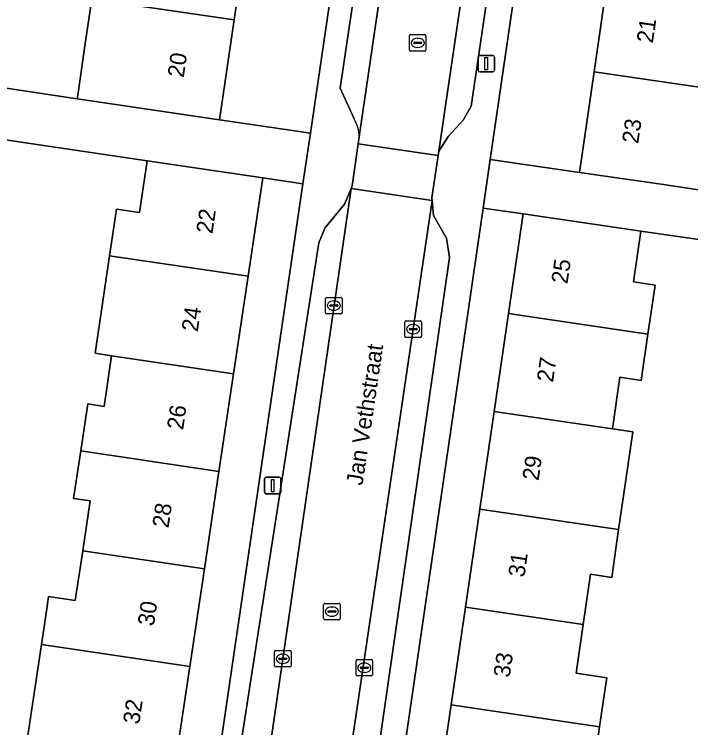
# Model space of a CAD drawing. Extents: x 163683 to 164494, y 382709 to 383872.
# Drawn here: x 164127.96 to 164168.99, y 382929.41 to 382972.71 of the extents above; entities that cross this region are included whole.
import ezdxf

# ---------------------------------------------------------------- set-up
doc = ezdxf.new("R2010")
doc.units = 0
for name, color, linetype in [('IMGEO_Erf', 7, 'Continuous'), ('IMGEO_Kolk', 7, 'Continuous'), ('IMGEO_Lichtmast', 7, 'Continuous'), ('IMGEO_Openbare_ruimte_label', 7, 'Continuous'), ('IMGEO_Pand', 7, 'Continuous'), ('IMGEO_Pand_nummerreeks', 7, 'Continuous'), ('IMGEO_Parkeervlak_open', 7, 'Continuous'), ('IMGEO_Rijbaan_lokaal_open', 7, 'Continuous'), ('IMGEO_Rioolput', 7, 'Continuous'), ('IMGEO_Voetpad_open', 7, 'Continuous')]:
    doc.layers.add(name, color=color, linetype=linetype)

msp = doc.modelspace()

# ---------------------------------------------------------------- linework, layer by layer
at = {"layer": 'IMGEO_Erf'}
for points in [[(164150.98, 383000), (164151.195, 383001.469), (164145.689, 383002.289), (164145.353, 383000), (164144.775, 382996.057), (164143.907, 382990.134), (164143.039, 382984.212), (164142.171, 382978.289), (164141.303, 382972.366), (164140.413, 382966.297), (164145.92, 382965.49)], [(164165.72, 382987.017), (164166.584, 382992.955), (164167.47, 382999.044), (164162.059, 382999.803), (164156.836, 382963.9), (164162.243, 382963.113), (164163.129, 382969.204), (164163.993, 382975.142), (164164.857, 382981.08)], [(164145.469, 382962.412), (164143.034, 382962.775), (164142.144, 382956.805), (164141.26, 382950.884), (164140.377, 382944.964), (164139.494, 382939.044), (164138.611, 382933.124), (164137.706, 382927.054), (164140.229, 382926.679)], [(164157.067, 382948.608), (164157.939, 382954.544), (164158.826, 382960.588), (164156.406, 382960.944), (164151.193, 382925.112), (164153.565, 382924.757), (164154.452, 382930.798), (164155.324, 382936.735), (164156.195, 382942.671)]]:
    msp.add_lwpolyline(points, close=True, dxfattribs=at)
for points in [[(164124.755, 382977.888), (164123.807, 382971.646), (164127.214, 382971.131), (164126.79, 382968.33), (164131.776, 382967.569), (164131.811, 382967.807), (164132.27, 382970.928), (164132.669, 382973.639)], [(164128.706, 382928.397), (164129.611, 382934.465), (164129.912, 382936.48), (164130.044, 382937.367), (164131.662, 382937.125), (164132.112, 382940.144), (164132.564, 382943.175), (164131.561, 382943.325), (164131.992, 382946.215), (164132.417, 382949.06), (164133.404, 382948.913), (164133.862, 382951.987), (164132.861, 382952.136), (164133.331, 382955.286), (164133.744, 382958.057), (164134.167, 382960.889), (164135.555, 382960.682), (164136.023, 382963.821), (164126.324, 382965.242)], [(164174.952, 382958.25), (164165.962, 382959.54), (164165.515, 382956.464), (164166.828, 382956.273), (164166.395, 382953.298), (164165.987, 382950.489), (164164.702, 382950.676), (164164.247, 382947.549), (164165.482, 382947.367), (164165.059, 382944.456), (164164.619, 382941.43), (164164.198, 382938.536), (164162.91, 382938.724), (164162.468, 382935.682), (164162.037, 382932.72), (164163.906, 382932.447), (164163.768, 382931.519), (164163.462, 382929.47), (164163.03, 382926.573)]]:
    msp.add_lwpolyline(points, dxfattribs=at)
at = {"layer": 'IMGEO_Kolk'}
for p, q in [((164146.841, 382954.601), (164146.841, 382955.453)), ((164146.916, 382955.527), (164147.768, 382955.527)), ((164147.842, 382955.453), (164147.842, 382954.601)), ((164147.1, 382955.021), (164147.1, 382955.033)), ((164147.538, 382954.984), (164147.14, 382954.984)), ((164147.143, 382955.07), (164147.541, 382955.07)), ((164147.329, 382955.307), (164147.354, 382955.307)), ((164147.584, 382955.033), (164147.584, 382955.021)), ((164147.768, 382954.527), (164146.916, 382954.527)), ((164147.352, 382954.747), (164147.327, 382954.747)), ((164151.732, 382954.099), (164152.584, 382954.099)), ((164151.657, 382953.173), (164151.657, 382954.025)), ((164152.145, 382953.879), (164152.17, 382953.879)), ((164152.658, 382954.025), (164152.658, 382953.173)), ((164151.916, 382953.593), (164151.916, 382953.605)), ((164152.354, 382953.556), (164151.956, 382953.556)), ((164151.959, 382953.642), (164152.357, 382953.642)), ((164152.168, 382953.319), (164152.143, 382953.319)), ((164152.4, 382953.605), (164152.4, 382953.593)), ((164152.584, 382953.099), (164151.732, 382953.099)), ((164143.747, 382933.171), (164143.747, 382934.023)), ((164143.822, 382934.097), (164144.674, 382934.097)), ((164144.235, 382933.877), (164144.26, 382933.877)), ((164144.748, 382934.023), (164144.748, 382933.171)), ((164144.006, 382933.591), (164144.006, 382933.603)), ((164144.444, 382933.554), (164144.046, 382933.554)), ((164144.049, 382933.64), (164144.447, 382933.64)), ((164144.258, 382933.317), (164144.233, 382933.317)), ((164144.49, 382933.603), (164144.49, 382933.591)), ((164148.696, 382932.624), (164148.696, 382933.476)), ((164148.771, 382933.55), (164149.623, 382933.55)), ((164149.184, 382933.33), (164149.209, 382933.33)), ((164149.697, 382933.476), (164149.697, 382932.624)), ((164144.674, 382933.097), (164143.822, 382933.097)), ((164148.955, 382933.044), (164148.955, 382933.056)), ((164149.393, 382933.007), (164148.995, 382933.007)), ((164148.998, 382933.093), (164149.396, 382933.093)), ((164149.439, 382933.056), (164149.439, 382933.044)), ((164149.623, 382932.55), (164148.771, 382932.55)), ((164149.207, 382932.77), (164149.182, 382932.77))]:
    msp.add_line(p, q, dxfattribs=at)
for points in [[(164146.841, 382954.601), (164146.841, 382955.453)], [(164146.916, 382955.527), (164147.768, 382955.527)], [(164147.842, 382955.453), (164147.842, 382954.601)], [(164147.768, 382954.527), (164146.916, 382954.527)], [(164151.732, 382954.099), (164152.584, 382954.099)], [(164151.657, 382953.173), (164151.657, 382954.025)], [(164152.658, 382954.025), (164152.658, 382953.173)], [(164152.584, 382953.099), (164151.732, 382953.099)], [(164143.747, 382933.171), (164143.747, 382934.023)], [(164143.822, 382934.097), (164144.674, 382934.097)], [(164144.748, 382934.023), (164144.748, 382933.171)], [(164148.696, 382932.624), (164148.696, 382933.476)], [(164148.771, 382933.55), (164149.623, 382933.55)], [(164149.697, 382933.476), (164149.697, 382932.624)], [(164144.674, 382933.097), (164143.822, 382933.097)], [(164149.623, 382932.55), (164148.771, 382932.55)]]:
    msp.add_lwpolyline(points, dxfattribs=at)
for centre, radius, start, end in [((164146.918, 382955.451), 0.0765, 91.552, 178.448), ((164146.918, 382955.451), 0.0765, 91.552, 178.448), ((164147.766, 382955.451), 0.0765, 1.552, 88.448), ((164147.766, 382955.451), 0.0765, 1.552, 88.448), ((164147.14, 382955.03), 0.0403, 85.8775, 175.7526), ((164147.137, 382955.02), 0.0366, 178.938, 274.7102), ((164147.541, 382955.027), 0.043, 264.8664, 352.4533), ((164147.545, 382955.032), 0.0386, 1.7309, 96.639), ((164146.918, 382954.603), 0.0765, 181.552, 268.448), ((164146.918, 382954.603), 0.0765, 181.552, 268.448), ((164147.766, 382954.603), 0.0765, 271.552, 358.448), ((164147.766, 382954.603), 0.0765, 271.552, 358.448), ((164151.734, 382954.023), 0.0765, 91.552, 178.448), ((164151.734, 382954.023), 0.0765, 91.552, 178.448), ((164152.582, 382954.023), 0.0765, 1.552, 88.448), ((164152.582, 382954.023), 0.0765, 1.552, 88.448), ((164151.956, 382953.602), 0.0403, 85.8775, 175.7526), ((164151.953, 382953.592), 0.0366, 178.938, 274.7102), ((164152.357, 382953.599), 0.043, 264.8664, 352.4533), ((164152.361, 382953.604), 0.0386, 1.7309, 96.639), ((164151.734, 382953.175), 0.0765, 181.552, 268.448), ((164151.734, 382953.175), 0.0765, 181.552, 268.448), ((164152.582, 382953.175), 0.0765, 271.552, 358.448), ((164152.582, 382953.175), 0.0765, 271.552, 358.448), ((164143.824, 382934.021), 0.0765, 91.552, 178.448), ((164143.824, 382934.021), 0.0765, 91.552, 178.448), ((164144.672, 382934.021), 0.0765, 1.552, 88.448), ((164144.672, 382934.021), 0.0765, 1.552, 88.448), ((164144.046, 382933.6), 0.0403, 85.8775, 175.7526), ((164144.043, 382933.59), 0.0366, 178.938, 274.7102), ((164144.447, 382933.597), 0.043, 264.8664, 352.4533), ((164144.451, 382933.602), 0.0386, 1.7309, 96.639), ((164148.773, 382933.474), 0.0765, 91.552, 178.448), ((164148.773, 382933.474), 0.0765, 91.552, 178.448), ((164149.621, 382933.474), 0.0765, 1.552, 88.448), ((164149.621, 382933.474), 0.0765, 1.552, 88.448), ((164143.824, 382933.173), 0.0765, 181.552, 268.448), ((164143.824, 382933.173), 0.0765, 181.552, 268.448), ((164144.672, 382933.173), 0.0765, 271.552, 358.448), ((164144.672, 382933.173), 0.0765, 271.552, 358.448), ((164148.995, 382933.053), 0.0403, 85.8775, 175.7526), ((164148.992, 382933.043), 0.0366, 178.938, 274.7102), ((164149.396, 382933.05), 0.043, 264.8664, 352.4533), ((164149.4, 382933.055), 0.0386, 1.7309, 96.639), ((164148.773, 382932.626), 0.0765, 181.552, 268.448), ((164148.773, 382932.626), 0.0765, 181.552, 268.448), ((164149.621, 382932.626), 0.0765, 271.552, 358.448), ((164149.621, 382932.626), 0.0765, 271.552, 358.448)]:
    msp.add_arc(centre, radius, start, end, dxfattribs=at)
for centre, major_axis, ratio, start_param, end_param in [((164147.328, 382955.027), (-0.387, 0.002), 0.722429, 4.712389, 7.853982), ((164147.353, 382955.027), (-0.39, 0.002), 0.717154, 1.570796, 4.712389), ((164152.144, 382953.599), (-0.387, 0.002), 0.722429, 4.712389, 7.853982), ((164152.169, 382953.599), (-0.39, 0.002), 0.717154, 1.570796, 4.712389), ((164144.234, 382933.597), (-0.387, 0.002), 0.722429, 4.712389, 7.853982), ((164144.259, 382933.597), (-0.39, 0.002), 0.717154, 1.570796, 4.712389), ((164149.183, 382933.05), (-0.387, 0.002), 0.722429, 4.712389, 7.853982), ((164149.208, 382933.05), (-0.39, 0.002), 0.717154, 1.570796, 4.712389)]:
    msp.add_ellipse(centre, major_axis=major_axis, ratio=ratio, start_param=start_param, end_param=end_param, dxfattribs=at)
at = {"layer": 'IMGEO_Lichtmast'}
for p, q in [((164156.193, 382970.205), (164156.983, 382970.205)), ((164156.983, 382970.205), (164156.193, 382970.205)), ((164156.093, 382969.305), (164156.093, 382970.105)), ((164156.093, 382970.105), (164156.093, 382969.305)), ((164157.083, 382970.105), (164157.083, 382969.305)), ((164157.083, 382969.305), (164157.083, 382970.105)), ((164156.983, 382969.205), (164156.193, 382969.205)), ((164156.193, 382969.205), (164156.983, 382969.205)), ((164143.241, 382944.608), (164144.031, 382944.608)), ((164144.031, 382944.608), (164143.241, 382944.608)), ((164143.141, 382943.708), (164143.141, 382944.508)), ((164143.141, 382944.508), (164143.141, 382943.708)), ((164144.131, 382944.508), (164144.131, 382943.708)), ((164144.131, 382943.708), (164144.131, 382944.508)), ((164144.031, 382943.608), (164143.241, 382943.608)), ((164143.241, 382943.608), (164144.031, 382943.608))]:
    msp.add_line(p, q, dxfattribs=at)
for points in [[(164156.513, 382970.08), (164156.663, 382970.08), (164156.663, 382969.33), (164156.513, 382969.33), (164156.513, 382970.08)], [(164143.561, 382944.483), (164143.711, 382944.483), (164143.711, 382943.733), (164143.561, 382943.733), (164143.561, 382944.483)]]:
    msp.add_lwpolyline(points, dxfattribs=at)
for centre, start, end in [((164156.193, 382970.105), 90, 180), ((164156.193, 382970.105), 90, 180), ((164156.983, 382970.105), 0, 90), ((164156.983, 382970.105), 360, 90), ((164156.193, 382969.305), 180, 270), ((164156.193, 382969.305), 180, 270), ((164156.983, 382969.305), 270, 0), ((164156.983, 382969.305), 270, 0), ((164143.241, 382944.508), 90, 180), ((164143.241, 382944.508), 90, 180), ((164144.031, 382944.508), 0, 90), ((164144.031, 382944.508), 360, 90), ((164143.241, 382943.708), 180, 270), ((164143.241, 382943.708), 180, 270), ((164144.031, 382943.708), 270, 0), ((164144.031, 382943.708), 270, 0)]:
    msp.add_arc(centre, 0.1, start, end, dxfattribs=at)
at = {"layer": 'IMGEO_Pand'}
for points in [[(164142.171, 382978.289), (164134.655, 382979.397), (164133.541, 382979.561), (164133.11, 382976.634), (164132.669, 382973.639), (164141.303, 382972.366)], [(164171.25, 382974.086), (164163.993, 382975.142), (164163.129, 382969.204), (164171.591, 382967.973), (164174.826, 382967.502), (164175.221, 382970.212), (164171.985, 382970.683), (164172.016, 382970.894), (164170.811, 382971.069)], [(164141.303, 382972.366), (164132.669, 382973.639), (164132.27, 382970.928), (164131.811, 382967.807), (164131.776, 382967.569), (164132.895, 382967.404), (164135.467, 382967.025), (164140.413, 382966.297)], [(164171.591, 382967.973), (164163.129, 382969.204), (164162.243, 382963.113), (164167.191, 382962.393), (164169.473, 382962.061), (164169.929, 382965.201), (164171.161, 382965.022)], [(164133.744, 382958.057), (164142.144, 382956.805), (164143.034, 382962.775), (164138.089, 382963.513), (164136.023, 382963.821), (164135.555, 382960.682), (164134.167, 382960.889)], [(164166.395, 382953.298), (164166.828, 382956.273), (164165.515, 382956.464), (164165.962, 382959.54), (164163.773, 382959.861), (164158.826, 382960.588), (164157.939, 382954.544)], [(164142.144, 382956.805), (164133.744, 382958.057), (164133.331, 382955.286), (164132.861, 382952.136), (164133.862, 382951.987), (164141.26, 382950.884)], [(164166.395, 382953.298), (164157.939, 382954.544), (164157.067, 382948.608), (164164.247, 382947.549), (164164.702, 382950.676), (164165.987, 382950.489)], [(164141.26, 382950.884), (164133.862, 382951.987), (164133.404, 382948.913), (164132.417, 382949.06), (164131.992, 382946.215), (164140.377, 382944.964)], [(164164.247, 382947.549), (164157.067, 382948.608), (164156.195, 382942.671), (164164.619, 382941.43), (164165.059, 382944.456), (164165.482, 382947.367)], [(164132.112, 382940.144), (164139.494, 382939.044), (164140.377, 382944.964), (164131.992, 382946.215), (164131.561, 382943.325), (164132.564, 382943.175)], [(164164.619, 382941.43), (164156.195, 382942.671), (164155.324, 382936.735), (164162.468, 382935.682), (164162.91, 382938.724), (164164.198, 382938.536)], [(164132.112, 382940.144), (164131.662, 382937.125), (164130.044, 382937.367), (164129.912, 382936.48), (164129.611, 382934.465), (164138.611, 382933.124), (164139.494, 382939.044)], [(164162.468, 382935.682), (164155.324, 382936.735), (164154.452, 382930.798), (164163.462, 382929.47), (164163.768, 382931.519), (164163.906, 382932.447), (164162.037, 382932.72)], [(164138.611, 382933.124), (164129.611, 382934.465), (164128.706, 382928.397), (164130.289, 382928.161), (164137.706, 382927.054)], [(164163.462, 382929.47), (164154.452, 382930.798), (164153.565, 382924.757), (164160.986, 382923.667), (164161.447, 382926.805), (164163.03, 382926.573)]]:
    msp.add_lwpolyline(points, close=True, dxfattribs=at)
at = {"layer": 'IMGEO_Parkeervlak_open'}
for points in [[(164148.89, 382965.262), (164153.797, 382998.804), (164153.297, 382998.155), (164152.575, 382997.555), (164151.931, 382996.613), (164147.73, 382968.221), (164148.575, 382966.357)], [(164158.474, 382996.758), (164153.712, 382964.394), (164154.305, 382965.31), (164155.191, 382966.279), (164155.683, 382967.132), (164159.573, 382993.627)], [(164148.388, 382962.134), (164147.997, 382961.185), (164146.796, 382959.732), (164146.444, 382958.829), (164140.823, 382922.696), (164140.91, 382922.339), (164140.017, 382917.209)], [(164141.145, 382914.701), (164142.339, 382922.07), (164143.2, 382926.357), (164148.388, 382962.134)], [(164148.471, 382915.706), (164148.75, 382918.131), (164149.279, 382922.725), (164154.37, 382957.956), (164154.188, 382959.124), (164153.396, 382960.493), (164153.311, 382961.412), (164148.02, 382925.587), (164146.817, 382913.836)]]:
    msp.add_lwpolyline(points, dxfattribs=at)
msp.add_arc((164146.515, 382965.172), 2.376, 2.1782, 29.9199, dxfattribs=at)
at = {"layer": 'IMGEO_Rijbaan_lokaal_open'}
msp.add_lwpolyline([(164161.486, 383014.587), (164161.64, 383015.622), (164162.802, 383023.844), (164157.512, 383024.592), (164154.966, 383006.746), (164154.423, 383002.944), (164154.003, 383000), (164153.797, 382998.804), (164148.89, 382965.262), (164148.828, 382964.839), (164153.673, 382964.128), (164153.712, 382964.394), (164158.474, 382996.758), (164158.492, 382997.006), (164158.548, 382997.381)], dxfattribs=at)
for points in [[(164148.388, 382962.134), (164153.311, 382961.412), (164153.297, 382961.565), (164153.673, 382964.128), (164148.828, 382964.839), (164148.456, 382962.298)], [(164148.02, 382925.587), (164153.311, 382961.412), (164148.388, 382962.134), (164143.2, 382926.357), (164142.339, 382922.07), (164141.145, 382914.701), (164141.032, 382913.929), (164146.709, 382913.077), (164146.817, 382913.836)]]:
    msp.add_lwpolyline(points, close=True, dxfattribs=at)
at = {"layer": 'IMGEO_Rioolput'}
for p, q in [((164152.008, 382971.474), (164152.86, 382971.474)), ((164151.933, 382970.548), (164151.933, 382971.4)), ((164152.192, 382970.968), (164152.192, 382970.98)), ((164152.235, 382971.017), (164152.633, 382971.017)), ((164152.421, 382971.254), (164152.446, 382971.254)), ((164152.676, 382970.98), (164152.676, 382970.968)), ((164152.934, 382971.4), (164152.934, 382970.548)), ((164152.63, 382970.931), (164152.232, 382970.931)), ((164152.444, 382970.694), (164152.419, 382970.694)), ((164152.86, 382970.474), (164152.008, 382970.474)), ((164146.727, 382936.03), (164146.727, 382936.882)), ((164146.802, 382936.956), (164147.654, 382936.956)), ((164147.728, 382936.882), (164147.728, 382936.03)), ((164146.986, 382936.45), (164146.986, 382936.462)), ((164147.424, 382936.413), (164147.026, 382936.413)), ((164147.029, 382936.499), (164147.427, 382936.499)), ((164147.215, 382936.736), (164147.24, 382936.736)), ((164147.47, 382936.462), (164147.47, 382936.45)), ((164147.654, 382935.956), (164146.802, 382935.956)), ((164147.238, 382936.176), (164147.213, 382936.176))]:
    msp.add_line(p, q, dxfattribs=at)
for points in [[(164152.008, 382971.474), (164152.86, 382971.474)], [(164151.933, 382970.548), (164151.933, 382971.4)], [(164152.934, 382971.4), (164152.934, 382970.548)], [(164152.86, 382970.474), (164152.008, 382970.474)], [(164146.727, 382936.03), (164146.727, 382936.882)], [(164146.802, 382936.956), (164147.654, 382936.956)], [(164147.728, 382936.882), (164147.728, 382936.03)], [(164147.654, 382935.956), (164146.802, 382935.956)]]:
    msp.add_lwpolyline(points, dxfattribs=at)
for centre, radius, start, end in [((164152.01, 382971.398), 0.0765, 91.552, 178.448), ((164152.01, 382971.398), 0.0765, 91.552, 178.448), ((164152.858, 382971.398), 0.0765, 1.552, 88.448), ((164152.858, 382971.398), 0.0765, 1.552, 88.448), ((164152.232, 382970.977), 0.0403, 85.8775, 175.7526), ((164152.637, 382970.979), 0.0386, 1.7309, 96.639), ((164152.01, 382970.55), 0.0765, 181.552, 268.448), ((164152.01, 382970.55), 0.0765, 181.552, 268.448), ((164152.229, 382970.967), 0.0366, 178.938, 274.7102), ((164152.633, 382970.974), 0.043, 264.8664, 352.4533), ((164152.858, 382970.55), 0.0765, 271.552, 358.448), ((164152.858, 382970.55), 0.0765, 271.552, 358.448), ((164146.804, 382936.88), 0.0765, 91.552, 178.448), ((164146.804, 382936.88), 0.0765, 91.552, 178.448), ((164147.652, 382936.88), 0.0765, 1.552, 88.448), ((164147.652, 382936.88), 0.0765, 1.552, 88.448), ((164147.026, 382936.459), 0.0403, 85.8775, 175.7526), ((164147.023, 382936.449), 0.0366, 178.938, 274.7102), ((164147.427, 382936.456), 0.043, 264.8664, 352.4533), ((164147.431, 382936.461), 0.0386, 1.7309, 96.639), ((164146.804, 382936.032), 0.0765, 181.552, 268.448), ((164146.804, 382936.032), 0.0765, 181.552, 268.448), ((164147.652, 382936.032), 0.0765, 271.552, 358.448), ((164147.652, 382936.032), 0.0765, 271.552, 358.448)]:
    msp.add_arc(centre, radius, start, end, dxfattribs=at)
for centre, major_axis, ratio, start_param, end_param in [((164152.42, 382970.974), (-0.387, 0.002), 0.722429, 4.712389, 7.853982), ((164152.445, 382970.974), (-0.39, 0.002), 0.717154, 1.570796, 4.712389), ((164147.214, 382936.456), (-0.387, 0.002), 0.722429, 4.712389, 7.853982), ((164147.239, 382936.456), (-0.39, 0.002), 0.717154, 1.570796, 4.712389)]:
    msp.add_ellipse(centre, major_axis=major_axis, ratio=ratio, start_param=start_param, end_param=end_param, dxfattribs=at)
at = {"layer": 'IMGEO_Voetpad_open'}
for points in [[(164156.242, 383029.553), (164155.571, 383027.702), (164155.367, 383026.302), (164154.282, 383018.881), (164155.244, 383018.714), (164153.476, 383006.694), (164152.925, 383002.989), (164151.45, 383003.208), (164151.417, 383002.982), (164151.195, 383001.469), (164150.98, 383000), (164145.92, 382965.49), (164145.469, 382962.412), (164140.229, 382926.679), (164139.939, 382924.7), (164139.409, 382922.626), (164138.954, 382920.045), (164138.554, 382917.653), (164137.738, 382912.877), (164140.818, 382912.448), (164141.032, 382913.929), (164141.145, 382914.701)], [(164148.575, 382966.357), (164147.73, 382968.221), (164151.931, 382996.613), (164152.575, 382997.555), (164153.297, 382998.155), (164153.797, 382998.804), (164154.003, 383000), (164154.423, 383002.944)], [(164146.817, 382913.836), (164146.709, 382913.077), (164146.503, 382911.594), (164149.432, 382911.153), (164149.954, 382915.563), (164150.234, 382917.907), (164150.916, 382923.211), (164151.193, 382925.112), (164156.406, 382960.944), (164156.836, 382963.9), (164162.059, 382999.803)], [(164159.573, 382993.627), (164155.683, 382967.132), (164155.191, 382966.279), (164154.305, 382965.31), (164153.712, 382964.394), (164153.673, 382964.128), (164153.297, 382961.565), (164153.311, 382961.412), (164153.396, 382960.493), (164154.188, 382959.124), (164154.37, 382957.956), (164149.279, 382922.725), (164148.75, 382918.131), (164148.471, 382915.706)], [(164126.324, 382965.242), (164136.023, 382963.821), (164138.089, 382963.513), (164143.034, 382962.775), (164145.469, 382962.412), (164145.92, 382965.49), (164140.413, 382966.297), (164135.467, 382967.025), (164132.895, 382967.404), (164131.776, 382967.569), (164126.79, 382968.33)], [(164140.017, 382917.209), (164140.91, 382922.339), (164140.823, 382922.696), (164146.444, 382958.829), (164146.796, 382959.732), (164147.997, 382961.185), (164148.388, 382962.134), (164148.456, 382962.298), (164148.828, 382964.839), (164148.89, 382965.262)], [(164169.473, 382962.061), (164167.191, 382962.393), (164162.243, 382963.113), (164156.836, 382963.9), (164156.406, 382960.944), (164158.826, 382960.588), (164163.773, 382959.861), (164165.962, 382959.54), (164174.952, 382958.25)]]:
    msp.add_lwpolyline(points, dxfattribs=at)
msp.add_arc((164146.515, 382965.172), 2.376, 2.1782, 29.9199, dxfattribs=at)

# ---------------------------------------------------------------- texts
at = {"layer": 'IMGEO_Openbare_ruimte_label'}
msp.add_text('Jan Vethstraat', height=1, rotation=81.5457, dxfattribs=at).set_placement((164149.081, 382944.079))
at = {"layer": 'IMGEO_Pand_nummerreeks'}
for s, rotation, p in [('21', 81.721, (164166.693, 382970.917)), ('20', 81.6637, (164138.237, 382968.824)), ('23', 81.7231, (164165.805, 382964.818)), ('22', 81.5165, (164139.976, 382959.35)), ('25', 81.647, (164161.513, 382956.308)), ('24', 81.5147, (164139.088, 382953.4)), ('27', 81.647, (164160.636, 382950.336)), ('26', 81.5165, (164138.2, 382947.446)), ('29', 81.6465, (164159.759, 382944.364)), ('28', 81.5165, (164137.312, 382941.496)), ('31', 81.647, (164158.899, 382938.504)), ('30', 81.5165, (164136.424, 382935.542)), ('33', 81.647, (164158.005, 382932.42)), ('32', 81.5147, (164135.536, 382929.583))]:
    msp.add_text(s, height=1, rotation=rotation, dxfattribs=at).set_placement(p)

doc.saveas('drawing.dxf')
